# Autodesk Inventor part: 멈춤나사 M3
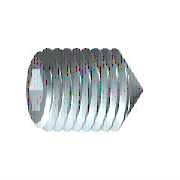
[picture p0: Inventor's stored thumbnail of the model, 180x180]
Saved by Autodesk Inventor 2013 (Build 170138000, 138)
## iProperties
IsCustomPart: 1
Created: 2012-02
Part Number: 멈춤나사 M3
Material: 강철, 연강
Description: 6각 소켓 머리 없는 멈춤 나사
Document SubType Name: Modeling
Standard: KS B 1028
Designer: test
Standards Organization: KS
Language: ko-KR
Size Designation: 원추점 M3x8
Categories: <MemberInstance><Categories><Category DisplayName="조임쇠" InternalName="e4da775c-781d-43d5-af7c-5136215cf5a6" Mnemonic="FSTN"><Category DisplayName="볼트" InternalN
Density: 1 g/cm^3
Author: test
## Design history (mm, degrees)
sketch "스케치1"
  geometry: L1 (0, 0)-(5.5, 0); L2 (8, 0.866)-(8, 1.5); L3 (8, 1.5)-(0, 1.5); L4 (8, 0.866)-(6, 0.866); L5 (6, 0.866)-(5.5, 0); L6 (0, -0.3)-(0, 1.8) reference; L7 (0, 1.5)-(0, 0)
  constraints: 13 end point, 3 parallel, 1 collinear, 1 perpendicular, 1 point on line
  dimensions: "d0" = 2 distance of L2.start L4.end (= INTI); "d1" = 60 deg angle of L5 L1; "d2" = 3 diameter of L3 L1 (= NND); "d3" = 1.73205 diameter of L4 L1 (= 1.1547 x SW); "d5" = 8 distance from line of L2 L3.end (= NLG)
revolve "본체" sketch "스케치1" stored, may be unused: angle "d6" = 90 deg
sketch "스케치2"
  geometry: L1 (-0.433, 0.75)-(0.433, 0.75); L2 (0.433, 0.75)-(0.866, 0); L3 (0.866, 0)-(0.433, -0.75); L4 (0.433, -0.75)-(-0.433, -0.75); L5 (-0.433, -0.75)-(-0.866, 0); L6 (-0.866, 0)-(-0.433, 0.75); 3 further points
  constraints: 12 end point, 1 coincident, 1 horizontal, 13 other
extrude "슬롯" join sketch "스케치2" taper "d7" = 0 deg; stored distance "d21" = 10
workaxis "Work Axis1"
workplane "Work Plane1"
sketch "스케치4"
  geometry: L1 (0, 0.15)-(-1.35, 1.5) reference; L2 (0, -0.15)-(-1.35, -1.5) reference; L3 (-1.35, -1.5)-(0.15, 0); L4 (-1.35, 1.5)-(0.15, 0); 2 further points
  constraints: 4 end point, 1 coincident, 1 collinear, 1 horizontal alignment
body "Solid1"
feature "스레드" dims "d12" = 8 (= NLG), "d13" = 0
chamfer "모따기1" distance "d8" = 1.35 (computed from NND, SPD, FAWI); stored, may be unused: angle "d9" = 45 deg (= FAWI), second distance "d34" = 1.35 (computed from NND, SPD, FAWI)
chamfer "모따기2" distance "d10" = 0.30673 (= -0.5 x GD1 + 0.5 x NND); stored, may be unused: angle "d11" = 45 deg (= FAWI), second distance "d35" = 0.30673 (= -0.5 x GD1 + 0.5 x NND)
other parameters: "NND" = 3 [user parameter; used in 5 equation terms], "NLG" = 8 [user parameter; used in 2 equation terms], "INTI" = 2 [user parameter; used in 1 equation term], "FAWI" = 45 deg [user parameter; used in 4 equation terms], "SW" = 1.5 [user parameter; used in 2 equation terms], "GD1" = 2.38655 (= THREADDIA - 1.2269 x PTC) [user parameter; used in 2 equation terms], "d4" = 0, "FAWI1" = 45 deg [user parameter], "SPD" = 0.3 [user parameter; used in 2 equation terms], "d36" = 0, "d37" = 0, "GUL" = 0.30673 (= 0.61345 x PTC) [user parameter], "TOA" = 30 deg [user parameter], "THREADDIA" = 3 [user parameter; used in 1 equation term], "PTC" = 0.5 [user parameter; used in 4 equation terms], "GAL" = 0.30673 (= 0.61345 x PTC) [user parameter], "E0" = 1.7325 (= 1.155 x SW) [user parameter]
